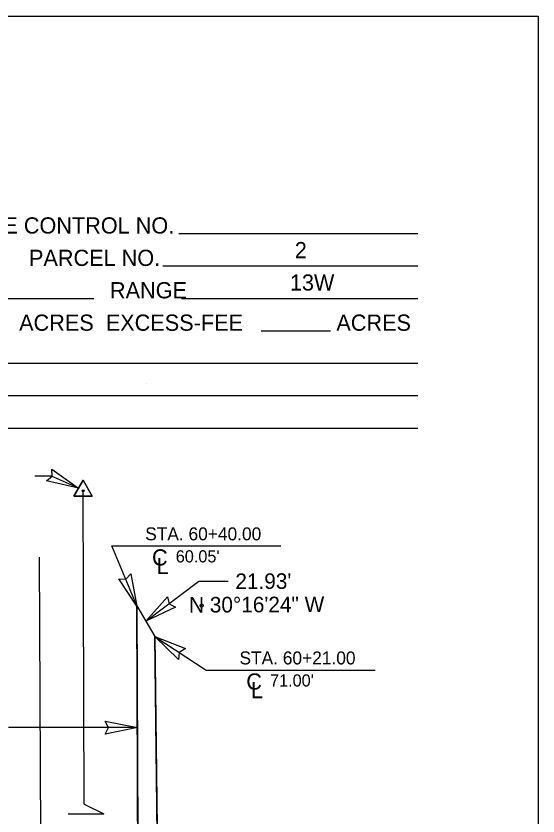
# Model space of a CAD drawing. Extents: x 23379288 to 23380138, y 6801100 to 6802500.
# Drawn here: x 23379815.5 to 23380137.8, y 6802006.9 to 6802500.5 of the extents above; entities that cross this region are included whole.
import ezdxf

# ---------------------------------------------------------------- set-up
doc = ezdxf.new("R2010")
doc.units = 0
for name, color, linetype in [('Alignment', 7, 'Continuous'), ('DisPlatCells', 7, 'Continuous'), ('DisPlatData', 7, 'Continuous'), ('DisROW Survey', 7, 'Continuous'), ('Draft_Plan_Labels', 7, 'Continuous'), ('Hatch', 7, 'Continuous'), ('Kevin', 7, 'Continuous'), ('Kevin_Points', 7, 'Continuous'), ('Kevin_Text', 7, 'Continuous'), ('Level 60', 7, 'Continuous'), ('SurPointsNonDTM', 7, 'Continuous'), ('SurSectionCorner', 7, 'Continuous')]:
    doc.layers.add(name, color=color, linetype=linetype)

msp = doc.modelspace()

# ---------------------------------------------------------------- linework, layer by layer
at = {"layer": 'Alignment'}
msp.add_line((23379834.18, 6801379.72), (23379829.94, 6802166.67), dxfattribs=at)
at = {"layer": 'DisPlatCells'}
for p, q in [((23379916, 6802366.26), (23380063.5, 6802366.26)), ((23379906.16, 6802346.26), (23380063.5, 6802346.26)), ((23379680.68, 6802326.27), (23379863.49, 6802326.27)), ((23379917.69, 6802326.27), (23380063.5, 6802326.27)), ((23379966.87, 6802306.27), (23380009.74, 6802306.27)), ((23379439.22, 6802286.27), (23380063.5, 6802286.27)), ((23379439.22, 6802266.26), (23380063.5, 6802266.26)), ((23379328.47, 6802246.26), (23380063.5, 6802246.26)), ((23379857.62, 6802014.25), (23379869.6, 6802008.33)), ((23379857.62, 6802014.25), (23379869.6, 6802008.33)), ((23379847.6, 6802008.23), (23379869.6, 6802008.33)), ((23379847.6, 6802008.23), (23379869.6, 6802008.33))]:
    msp.add_line(p, q, dxfattribs=at)
at = {"layer": 'DisROW Survey'}
msp.add_line((23379895.97, 6802273.82), (23379896, 6802273.82), dxfattribs=at)
msp.add_line((23379895.97, 6802273.82), (23379896, 6802273.82), dxfattribs=at)
msp.add_line((23379895.97, 6802273.82), (23379896, 6802273.82), dxfattribs=at)
msp.add_line((23379895.97, 6802273.82), (23379896, 6802273.82), dxfattribs=at)
msp.add_line((23379895.97, 6802273.82), (23379896, 6802273.82), dxfattribs=at)
at = {"layer": 'Draft_Plan_Labels'}
for points in [[(23379834.33, 6802213.67), (23379837.74, 6802216.54), (23379837.68, 6802220.93), (23379854.07, 6802209.12)], [(23379878.92, 6802153.31), (23379883.37, 6802153.05), (23379886.34, 6802156.29), (23379890.15, 6802136.45)], [(23379909.09, 6802142.21), (23379909.98, 6802137.84), (23379913.87, 6802135.8), (23379895.68, 6802127.02)], [(23379920.07, 6802110.21), (23379916.28, 6802107.87), (23379915.7, 6802103.52), (23379901.21, 6802117.59)], [(23379870.61, 6802057.44), (23379872.51, 6802061.48), (23379870.61, 6802065.44), (23379890.44, 6802061.6)]]:
    msp.add_lwpolyline(points, close=True, dxfattribs=at)
at = {"layer": 'Hatch'}
msp.add_lwpolyline([(23379890.15, 6802136.53), (23379901.21, 6802117.59), (23379906.56, 6801679.61), (23379892.41, 6801551.53)], close=True, dxfattribs=at)
at = {"layer": 'Kevin'}
for p, q in [((23379890.11, 6802136.55), (23379874.64, 6802173.51)), ((23379895.68, 6802127.02), (23379928.35, 6802151.69)), ((23379928.35, 6802151.69), (23379946.5, 6802151.69)), ((23379901.21, 6802117.59), (23379932.85, 6802096.95)), ((23379890.44, 6802061.6), (23379810.9, 6802061.51))]:
    msp.add_line(p, q, dxfattribs=at)
at = {"layer": 'Kevin_Points'}
msp.add_line((23379857.62, 6802014.25), (23379856.87, 6802208.12), dxfattribs=at)
at = {"layer": 'Kevin_Text'}
for p, q in [((23379837.36, 6802216.62), (23379827.18, 6802216.62)), ((23379854.06, 6802209.12), (23379837.36, 6802216.64)), ((23379874.64, 6802173.51), (23379979.08, 6802173.51)), ((23379890.15, 6802136.53), (23379901.21, 6802117.59)), ((23379890.15, 6802136.53), (23379892.41, 6801551.53)), ((23379906.56, 6801679.61), (23379901.21, 6802117.59)), ((23379932.85, 6802096.95), (23380037.29, 6802096.95))]:
    msp.add_line(p, q, dxfattribs=at)
msp.add_lwpolyline([(23379851.24, 6802204.25), (23379856.88, 6802214.01), (23379862.51, 6802204.25)], close=True, dxfattribs=at)
at = {"layer": 'Level 60'}
for p, q in [((23379287.77, 6802500.47), (23380137.79, 6802500.47)), ((23380137.79, 6802500.47), (23380137.79, 6801100.45))]:
    msp.add_line(p, q, dxfattribs=at)
at = {"layer": 'SurPointsNonDTM'}
msp.add_circle((23379930.1, 6802136.74), 1, dxfattribs=at)
at = {"layer": 'SurSectionCorner'}
msp.add_lwpolyline([(23379851.24, 6802204.25), (23379862.51, 6802204.25), (23379856.88, 6802214.01), (23379851.24, 6802204.25)], dxfattribs=at)
msp.add_circle((23379856.88, 6802207.5), 0.644, dxfattribs=at)

# ---------------------------------------------------------------- texts
at = {"layer": 'DisPlatCells'}
for s, height, p in [('STATE CONTROL NO.', 10.0002, (23379773.48, 6802366.26)), ('PARCEL NO.', 10, (23379823.48, 6802346.26)), ('RANGE', 10, (23379873.48, 6802326.27)), ('ACRES  EXCESS-FEE', 10.0002, (23379817.39, 6802306.27)), ('ACRES', 10, (23380013.27, 6802306.27))]:
    msp.add_text(s, height=height, dxfattribs=at).set_placement(p)
at = {"layer": 'DisPlatData'}
for s, p in [('2', (23379987.63, 6802351.06)), ('13W', (23379984.63, 6802331.07))]:
    msp.add_text(s, height=9.96, dxfattribs=at).set_placement(p)
at = {"layer": 'Kevin'}
for s, p in [("21.93'", (23379950.92, 6802146.92)), ('N 30°16\'24" W', (23379922.32, 6802132.41))]:
    msp.add_text(s, height=9.6, rotation=0.2217, dxfattribs=at).set_placement(p)
at = {"layer": 'Kevin_Text'}
for s, height, p in [('STA. 60+40.00', 8.0002, (23379895.24, 6802176.98)), ('C', 10, (23379899.44, 6802161.43)), ("60.05'", 7.5, (23379914.11, 6802163.35)), ('L', 10, (23379902.33, 6802156.14)), ('STA. 60+21.00', 8.0002, (23379953.45, 6802100.43)), ('C', 10, (23379957.65, 6802084.88)), ("71.00'", 7.5, (23379972.32, 6802086.79)), ('L', 10, (23379960.54, 6802079.59))]:
    msp.add_text(s, height=height, dxfattribs=at).set_placement(p)

doc.saveas('drawing.dxf')
